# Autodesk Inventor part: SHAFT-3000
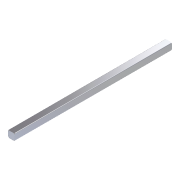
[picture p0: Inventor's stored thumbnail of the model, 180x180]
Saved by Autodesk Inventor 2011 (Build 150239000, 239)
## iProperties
Created: 2007-08
Part Number: SHAFT-3000
Material: Stainless Steel
Document SubType Name: Modeling
Density: 8.08 g/cm^3
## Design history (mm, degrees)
feature "Base1"
workaxis "Work Axis1"
  workplane "Work Plane1"
  workplane "Work Plane2"
workaxis "Work Axis2"
  workplane "Work Plane3"
  workplane "Work Plane4"
body "Solid1"
